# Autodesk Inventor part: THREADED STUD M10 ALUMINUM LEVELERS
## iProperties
Created: 2007-03
Part Number: THREADED STUD M10 ALUMINUM LEVELERS
Document SubType Name: Modeling
Designer: Andy Moles
Material: Steel
Mass: 44.008 g
Surface Area: 28.6789 cm^2
Volume: 5.60611 cm^3
Density: 7.85 g/cm^3
Author: Andy Moles
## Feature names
1. Revolution1
2. Extrusion1
3. Extrusion2
4. Chamfer1
